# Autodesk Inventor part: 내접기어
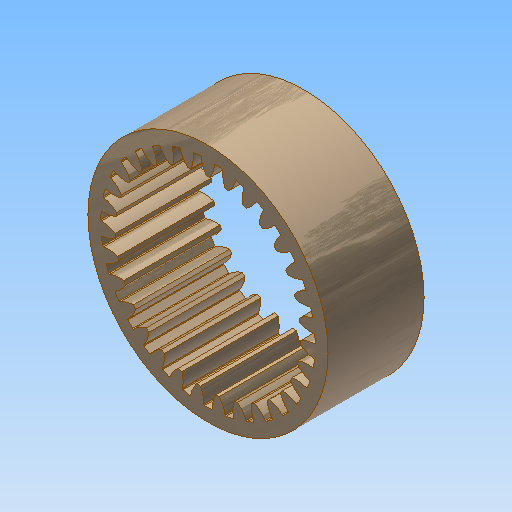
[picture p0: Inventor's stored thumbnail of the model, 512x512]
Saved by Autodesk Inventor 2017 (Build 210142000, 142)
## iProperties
Created: 2023-11
Part Number: 내접기어
Material: 알루미늄 6061
Document SubType Name: Modeling
Designer: mdu-01
Density: 1 g/cm^3
Appearance: 알루미늄 - 평지(1)
Author: mdu-01
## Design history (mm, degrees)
sketch "스케치1" dims "d0" = 75, "d1" = 62, "d3" = 2.5
  geometry: L1 (0, 0)-(0, 37.5); A1 r 29 centre (0, 0) between (0.57, 28.994) and (-0.57, 28.994); A2 r 8.747 centre (-6.664, 33.911) between (0.57, 28.994) and (2.07, 33.436); A3 r 8.747 centre (6.664, 33.911) between (-2.07, 33.436) and (-0.57, 28.994); A4 r 33.5 centre (0, 0) between (2.07, 33.436) and (-2.07, 33.436); 3 further points
  constraints: 9 point on circle, 4 centre point, 3 coincident, 3 symmetric about line, 2 end point, 1 vertical, 1 vertical alignment, 9 other
  dimensions: "d2" = 2 dimension on A1; "d4" = 1.57 distance from line of point (1.57, 30.96) L1; "d5" = 1 horizontal distance of A1.start point (1.57, 30.96); "d6" = 0.5 horizontal distance of A2.end point (1.57, 30.96)
extrude "돌출1" new body sketch "스케치1" distance "d7" = 30; taper "d8" = 0 deg
extrude "돌출2" join sketch "스케치1" distance "d9" = 30; taper "d10" = 0 deg
fillet "모깎기1" dims "d11" = 0.25
node "솔리드1"
pattern_circular "원형 패턴1" dims angle "d13" = 360 deg
